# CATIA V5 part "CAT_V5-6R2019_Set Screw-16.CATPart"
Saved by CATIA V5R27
Part number: Set Screw-16
Bounding box of the stored display mesh (mm): x -5.916 to 5.916, y -5.992 to 5.992, z -1.5 to 20.171
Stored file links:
  E:\_Deepak\2017_Deepak\CATIA\Resources\Tutorial Files\Tutorials\c16_catia_v5_6r2016_tut\Bench vice\CAT_V5-6R2016_Set Screw-16.CATPart
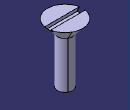
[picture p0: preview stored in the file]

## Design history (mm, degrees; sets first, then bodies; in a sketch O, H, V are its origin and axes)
Body1 (main body)
  Sketch1 on yz-plane, origin (0, 0, 0), H (0, 1, 0), V (0, 0, 1)
    point P1 (0, -1.5)
    line L1 (0, -1.5) -> (2.5, 0)
    point P2 (2.5, 0)
    line L2 (2.5, 0) -> (2.5, 16)
    line L3 (2.5, 16) -> (6, 20.1711)
    point P4 (6, 20.1711)
    line L4 (6, 20.1711) -> (0, 20.1711)
    point P5 (0, 20.1711)
    line L5 (0, 20.1711) -> (0, -1.5)
    length L2 = 16
    distance L2 L5 = 2.5
    distance H P1 = 1.5
    distance P4 L5 = 6
    angle L3 L5 = 40
    coincidence: P1 V, P2 H, P5 V
    vertical: L2 V, L5 V
    horizontal: L4 H
  Shaft1: profile Sketch1, axis edge of Sketch1, angle 360
  Sketch2 on yz-plane, origin (0, 0, 0), H (0, 1, 0), V (0, 0, 1)
    line L1 (-1, 20.1711) -> (1, 20.1711)
    line L2 (1, 20.1711) -> (1, 19.1711)
    line L3 (1, 19.1711) -> (-1, 19.1711)
    line L4 (-1, 19.1711) -> (-1, 20.1711)
    reference projected line E1 (-6, 20.1711) -> (6, 20.1711) from edge of Shaft1
    distance V L2 = 1
    length L1 = 2
    length L2 = 1
    horizontal: L1 H, L3 H
    vertical: L2 V, L4 V
    coincidence: L1 E1
  Pocket1: profile Sketch2, direction (-1, 0, 0), length 16, mirrored extent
